(* Logix 5000 project; controller RH_Cognex_PLC 1769-L16ER-BB1B rev 33.12; software revision 33.01 *)

TASK MainTask (continuous, watchdog 500 ms) : MainProgram

MODULES
   Local : 1769-L16ER-BB1B (PointIO 0, rev 33.12)
      IS7800 : vendor 678 type 100 code 276 (Ethernet 10.10.100.110, rev 11.1, Output RPI 60 ms)
      Discrete_IO : Embedded (PointIO 1, rev 33.11, Output RPI 20 ms)
END_MODULES

VAR_GLOBAL   (* controller tags *)
   Blank : SINT[128];
   Camera_JobName : STRING := '3_Test.job';
   Data_From_IS7800 : STRING := '$13$04$00$00$F0I$02$00$10$06$9E?$14$00$00$00Hello PLC. I$'m Job 3$00$00$00$00$00$00$00$00$00$00$00$00$00$00$00$00$00$00$00$00$00$00$00$00$00$00$00$00$00$00$00$00$00$00$00$00$00$00$00$00$00$00$00$00$00$00$00$00';
   Enable : BOOL := 1;
   IS7800_Job_Change : BOOL;
   IS7800_Job_Change_MSG : MESSAGE;
        MessageParameters(ServiceCode := 16#0010, LocalElement := SetJobData[0], ...)
   IS7800_Send_Data_CMD : BOOL;
   Job_Change_In_Process : BOOL;
   ONS : DINT;
   SetJobData : SINT[32] := ([0] := 10, [2] := 51, [3] := 95, [4] := 84, [5] := 101, [6] := 115, [7] := 116, [8] := 46, [9] := 106, [10] := 111, [11] := 98);
   Timer : TIMER := (PRE := 1000);
   Timer1 : TIMER := (PRE := 65);   // Hold Longer than RPI of AOP.
   TimerTriggerCMD : BOOL;
   TriggerCMD : BOOL;
END_VAR

PROGRAM MainProgram   (* main routine MainRoutine *)

ROUTINE IS7800_Job_Change   (* ladder *)
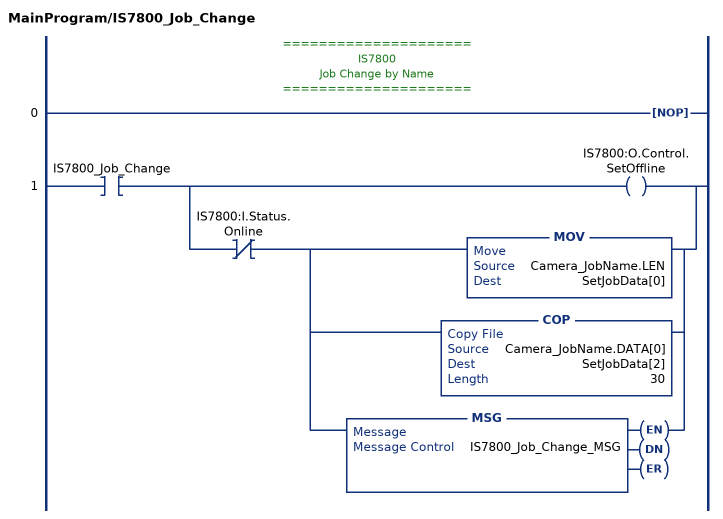
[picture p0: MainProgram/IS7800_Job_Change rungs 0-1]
   // =====================
   // IS7800
   // Job Change by Name
   // =====================
   0: NOP();
   1: XIC(IS7800_Job_Change)[OTE(IS7800:O.Control.SetOffline) ,XIO(IS7800:I.Status.Online) [MOV(Camera_JobName.LEN,SetJobData[0]) ,COP(Camera_JobName.DATA[0],SetJobData[2],30) ,MSG(IS7800_Job_Change_MSG) ] ];
END_ROUTINE

ROUTINE IS7800_Send_Receive_Data   (* ladder *)
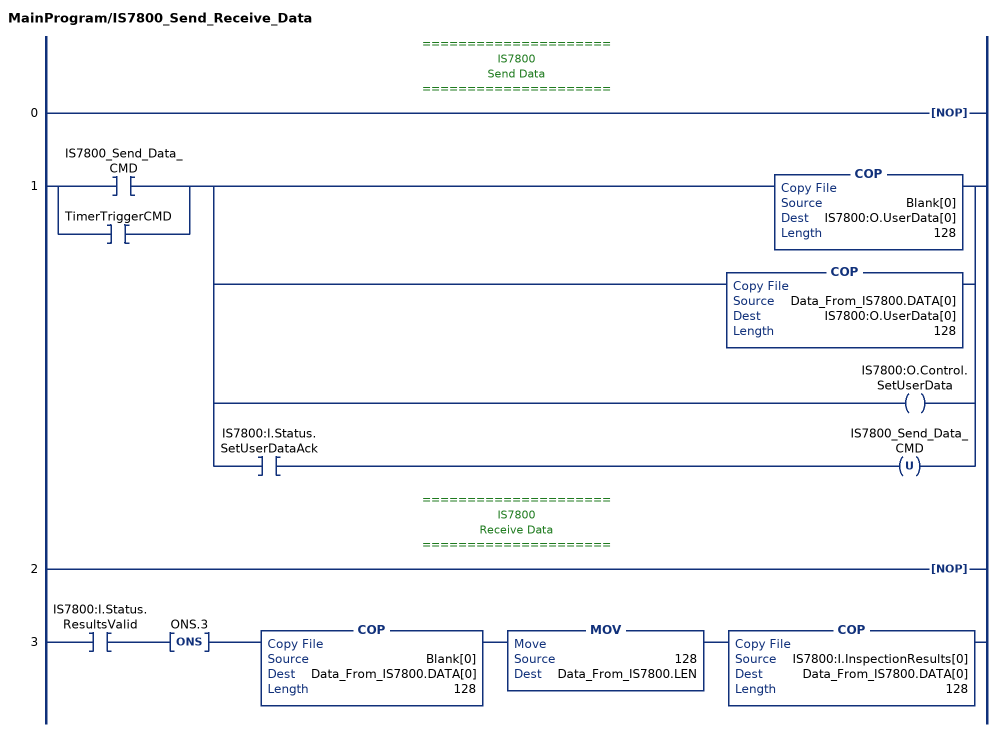
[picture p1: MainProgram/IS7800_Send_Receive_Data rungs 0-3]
   // =====================
   // IS7800
   // Send Data
   // =====================
   0: NOP();
   1: [XIC(IS7800_Send_Data_CMD) ,XIC(TimerTriggerCMD) ][COP(Blank[0],IS7800:O.UserData[0],128) ,COP(Data_From_IS7800.DATA[0],IS7800:O.UserData[0],128) ,OTE(IS7800:O.Control.SetUserData) ,XIC(IS7800:I.Status.SetUserDataAck) OTU(IS7800_Send_Data_CMD) ];
   // =====================
   // IS7800
   // Receive Data
   // =====================
   2: NOP();
   3: XIC(IS7800:I.Status.ResultsValid)ONS(ONS.3)COP(Blank[0],Data_From_IS7800.DATA[0],128)MOV(128,Data_From_IS7800.LEN)COP(IS7800:I.InspectionResults[0],Data_From_IS7800.DATA[0],128);
END_ROUTINE

ROUTINE IS7800_Trigger   (* ladder *)
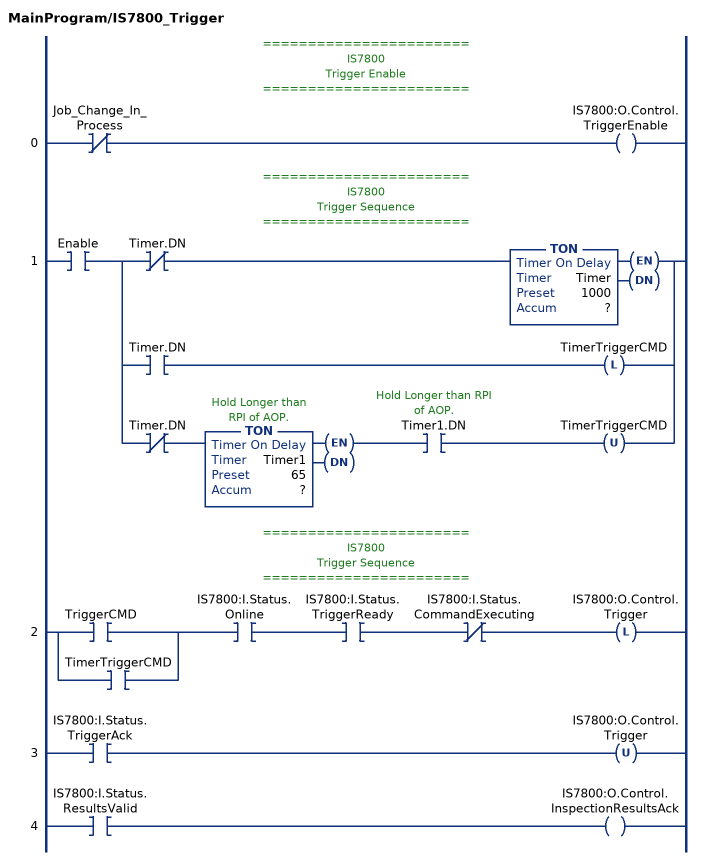
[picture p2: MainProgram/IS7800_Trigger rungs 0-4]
   // =======================
   // IS7800
   // Trigger Enable
   // =======================
   0: XIO(Job_Change_In_Process)OTE(IS7800:O.Control.TriggerEnable);
   // =======================
   // IS7800
   // Trigger Sequence
   // =======================
   1: XIC(Enable)[XIO(Timer.DN) TON(Timer,?,?) ,XIC(Timer.DN) OTL(TimerTriggerCMD) ,XIO(Timer.DN) TON(Timer1,?,?) XIC(Timer1.DN) OTU(TimerTriggerCMD) ];
   // =======================
   // IS7800
   // Trigger Sequence
   // =======================
   2: [XIC(TriggerCMD) ,XIC(TimerTriggerCMD) ]XIC(IS7800:I.Status.Online)XIC(IS7800:I.Status.TriggerReady)XIO(IS7800:I.Status.CommandExecuting)OTL(IS7800:O.Control.Trigger);
   3: XIC(IS7800:I.Status.TriggerAck)OTU(IS7800:O.Control.Trigger);
   4: XIC(IS7800:I.Status.ResultsValid)OTE(IS7800:O.Control.InspectionResultsAck);
END_ROUTINE

ROUTINE MainRoutine   (* ladder *)
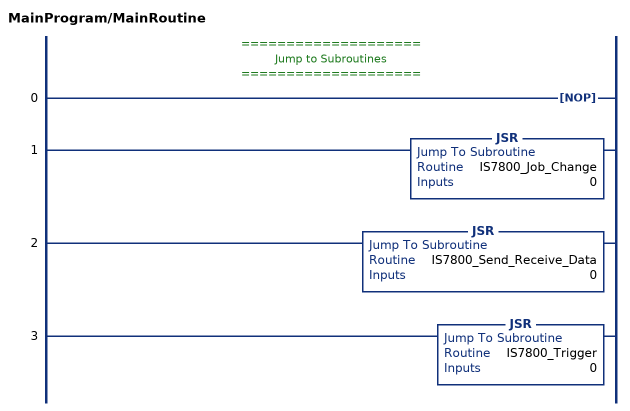
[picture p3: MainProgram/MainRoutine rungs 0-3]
   // ====================
   // Jump to Subroutines
   // ====================
   0: NOP();
   1: JSR(IS7800_Job_Change,0);
   2: JSR(IS7800_Send_Receive_Data,0);
   3: JSR(IS7800_Trigger,0);
END_ROUTINE
END_PROGRAM
